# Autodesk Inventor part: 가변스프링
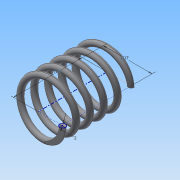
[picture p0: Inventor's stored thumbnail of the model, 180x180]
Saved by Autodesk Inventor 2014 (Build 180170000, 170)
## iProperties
Created: 2016-01
Part Number: 가변스프링
Material: Generic
Document SubType Name: Modeling
Designer: Administrator
Density: 1 g/cm^3
Appearance: Default
Author: Administrator
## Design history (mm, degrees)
sketch "스케치1"
  geometry: L1 (0, 0)-(8.5, 0); L2 (8.5, 0)-(8.5, 17.5); L3 (8.5, 17.5)-(0, 17.5); L4 (0, 17.5)-(0, 0); C1 r 1 at (8.5, 0)
  constraints: 8 end point, 2 parallel, 1 centre point, 1 coincident, 1 horizontal, 1 perpendicular
  dimensions: "d0" = 17.5 distance of L3.end L1.start (derived); "d1" = 17 diameter of L2 L4; "d2" = 2 diameter of C1
feature "코일1" pitch "d3" = 10; turns "d5" = 5; dims "d4" = 17.5 (= d0), "d6" = 0, angle "d7" = 90 deg, angle "d8" = 90 deg, "d9" = 0, "d10" = 0
node "작업 평면1"
sketch "스케치2"
  geometry: L1 (7.5, 0)-(9.5, 0) reference; 1 further point
  constraints: 1 horizontal alignment
extrude "돌출1" cut sketch "스케치2" stored distance "d12" = 10; taper "d13" = 0 deg
node "작업 평면2"
sketch "스케치3"
  geometry: L1 (-7.5, 0)-(-9.5, 0) reference; 1 further point
  constraints: 1 horizontal alignment
extrude "돌출2" cut sketch "스케치3" stored distance "d15" = 10; taper "d16" = 0 deg
node "솔리드1"
node "절단 모서리 투영1"
node "절단 모서리 투영2"
other parameters: "d11" = 0, "d14" = 17.5 (= d0)
